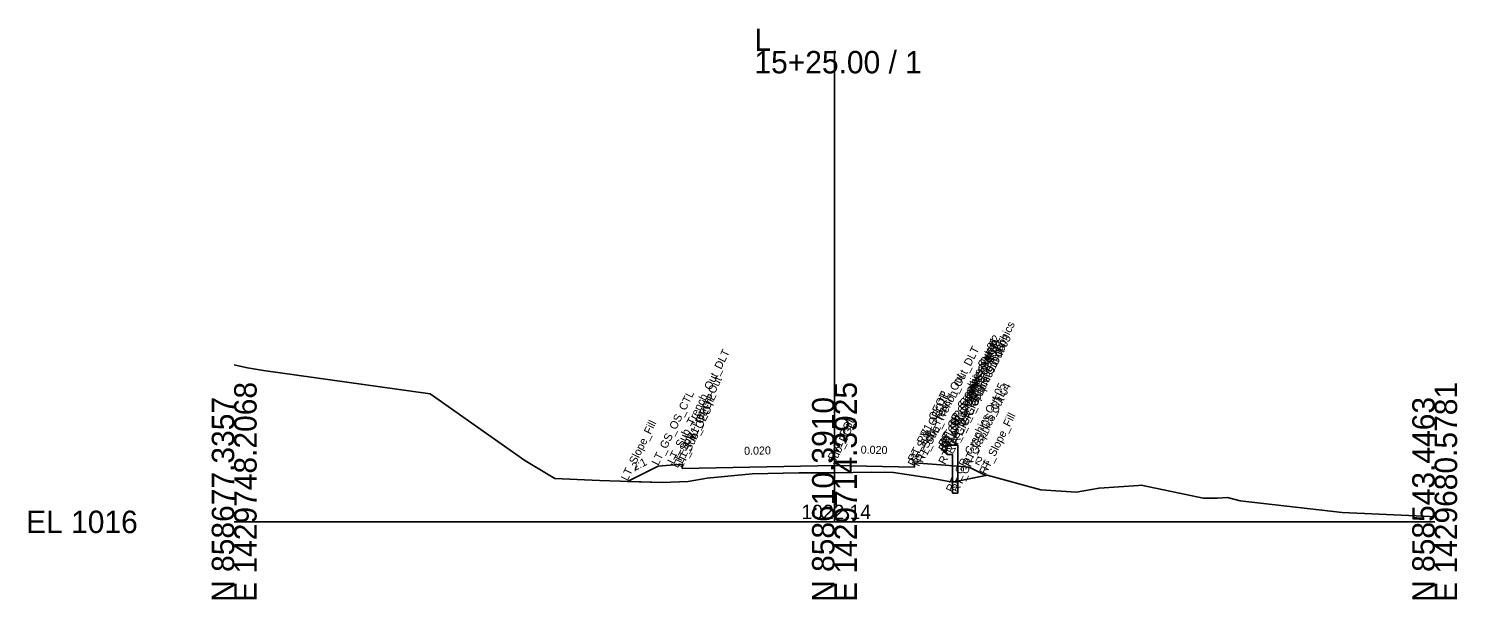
# Model space of a CAD drawing. Extents: x -26 to 176, y -10 to 13058.
# Drawn here: x -25.7 to 152.8, y 7490.3 to 7561.6 of the extents above; entities that cross this region are included whole.
import ezdxf

# ---------------------------------------------------------------- set-up
doc = ezdxf.new("R2010")
doc.units = 0
for name, color, linetype in [('Default', 7, 'Continuous'), ('Exist Cross Section Cell', 7, 'Continuous'), ('Exist XS Center Line Elevation Label', 7, 'Continuous'), ('Exist XS Ground Line', 7, 'Continuous'), ('Old_Level_50', 7, 'Continuous'), ('Prop CMT Guardrail Graphics', 7, 'Continuous'), ('Prop CMT Pvmt Course 1', 7, 'Continuous'), ('Prop CMT Pvmt Surface Shoulder', 7, 'Continuous'), ('Prop CMT Shld Paved Course 1', 7, 'Continuous'), ('Prop CMT Slope Grass', 7, 'Continuous'), ('Prop CMT Subgrade Earthwork', 7, 'Continuous'), ('Prop XS Dump Level', 7, 'Continuous'), ('Prop XS SE Text', 7, 'Continuous'), ('Prop XS Side Slope Text', 7, 'Continuous')]:
    doc.layers.add(name, color=color, linetype=linetype)

msp = doc.modelspace()

# ---------------------------------------------------------------- linework, layer by layer
at = {"layer": 'Exist Cross Section Cell'}
for p, q in [((75, 7500), (75, 7558.84)), ((0, 7500), (75, 7500)), ((75, 7500), (150, 7500))]:
    msp.add_line(p, q, dxfattribs=at)
at = {"layer": 'Exist XS Ground Line'}
msp.add_lwpolyline([(0, 7519.61), (0.71, 7519.47), (1.67, 7519.25), (3.65, 7518.93), (24.5, 7515.98), (36.31, 7507.68), (40.06, 7505.43), (45.63, 7505.15), (53.46, 7504.93), (56.72, 7505.03), (59.11, 7505.44), (64.72, 7506.01), (70.54, 7506.11), (73.64, 7506.13), (75, 7506.14), (79.63, 7506.19), (82.39, 7506.18), (87.07, 7505.47), (89.77, 7504.96), (94.08, 7505.83), (100.77, 7504.01), (105.19, 7503.69), (108.07, 7504.22), (113.01, 7504.56), (113.32, 7504.57), (119.69, 7503.26), (121.09, 7502.96), (122.86, 7502.97), (124.11, 7503.04), (125.68, 7502.64), (138.45, 7501.15), (148.62, 7500.7), (150, 7500.61)], dxfattribs=at)
at = {"layer": 'Old_Level_50'}
for points in [[(70.54, 7506.11), (73.64, 7506.13), (75, 7506.14), (79.63, 7506.19), (82.39, 7506.18), (87.07, 7505.47), (89.77, 7504.96), (93.93, 7505.79), (91.82, 7506.85), (88.82, 7507.09), (85, 7507.39), (85, 7506.85), (75, 7507.05), (55.98, 7506.67), (55.98, 7507.21), (52.98, 7506.97), (49.14, 7505.05), (53.46, 7504.93), (56.72, 7505.03), (59.11, 7505.44), (64.72, 7506.01)], [(91.82, 7506.85), (93.93, 7505.79), (89.77, 7504.96), (87.07, 7505.47), (82.39, 7506.18), (79.63, 7506.19), (75, 7506.14), (73.64, 7506.13), (70.54, 7506.11), (64.72, 7506.01), (59.11, 7505.44), (56.72, 7505.03), (53.46, 7504.93), (49.14, 7505.05), (52.98, 7506.97), (55.98, 7507.21), (55.98, 7506.67), (75, 7507.05), (85, 7506.85), (85, 7507.39), (88.82, 7507.09)]]:
    msp.add_lwpolyline(points, close=True, dxfattribs=at)
at = {"layer": 'Prop CMT Guardrail Graphics'}
for points in [[(90.42, 7509.59), (89.09, 7509.59), (88.82, 7509.3)], [(88.82, 7509.3), (89.09, 7509)], [(90.42, 7503.59), (90.42, 7509.59)], [(89.09, 7509), (88.82, 7508.71)], [(88.82, 7508.71), (89.09, 7508.42), (89.76, 7508.42)], [(89.76, 7508.42), (89.76, 7503.59)], [(89.76, 7503.59), (90.42, 7503.59)]]:
    msp.add_lwpolyline(points, dxfattribs=at)
at = {"layer": 'Prop CMT Pvmt Course 1'}
for points in [[(85, 7507.39), (85, 7506.85)], [(55.98, 7507.21), (55.98, 7506.67)], [(55.98, 7506.67), (75, 7507.05)], [(85, 7506.85), (75, 7507.05)]]:
    msp.add_lwpolyline(points, dxfattribs=at)
at = {"layer": 'Prop CMT Pvmt Surface Shoulder'}
for points in [[(85, 7507.39), (85, 7507.39)], [(55.98, 7507.21), (55.98, 7507.21)]]:
    msp.add_lwpolyline(points, dxfattribs=at)
at = {"layer": 'Prop CMT Shld Paved Course 1'}
for points in [[(85, 7507.39), (85, 7507.39)], [(85, 7506.85), (85, 7507.39)], [(55.98, 7507.21), (55.98, 7507.21)], [(55.98, 7506.67), (55.98, 7507.21)]]:
    msp.add_lwpolyline(points, dxfattribs=at)
at = {"layer": 'Prop CMT Slope Grass'}
for points in [[(85, 7507.39), (88.82, 7507.09)], [(55.98, 7507.21), (52.98, 7506.97), (49.14, 7505.05)], [(52.98, 7506.97), (49.14, 7505.05)], [(88.82, 7507.09), (91.82, 7506.85)], [(91.82, 7506.85), (93.93, 7505.79)]]:
    msp.add_lwpolyline(points, dxfattribs=at)
at = {"layer": 'Prop CMT Subgrade Earthwork'}
for points in [[(75, 7507.05), (55.98, 7506.67)], [(75, 7507.05), (85, 7506.85)]]:
    msp.add_lwpolyline(points, dxfattribs=at)

# ---------------------------------------------------------------- texts
at = {"layer": 'Default'}
msp.add_text('-', height=0.0001, dxfattribs=at).set_placement((0, 7500))
at = {"layer": 'Exist Cross Section Cell'}
for s, p in [('L', (65, 7558.84)), ('15+25.00 / 1', (65, 7556.04)), ('EL 1016', (-26, 7498.6))]:
    msp.add_text(s, height=2.8, dxfattribs=at).set_placement(p)
for s, p in [('E 1429748.2068', (2.8, 7490)), ('E 1429714.3925', (77.8, 7490)), ('E 1429680.5781', (152.8, 7490)), ('N 858677.3357', (0, 7490)), ('N 858610.3910', (75, 7490)), ('N 858543.4463', (150, 7490))]:
    msp.add_text(s, height=2.8, rotation=90, dxfattribs=at).set_placement(p)
at = {"layer": 'Exist XS Center Line Elevation Label'}
msp.add_text('1022.14', height=1.8, dxfattribs=at).set_placement((70.87, 7500.34))
msp.add_text('1022.14', height=1.8, dxfattribs=at).set_placement((70.87, 7500.34))
msp.add_text('1022.14', height=1.8, dxfattribs=at).set_placement((70.87, 7500.34))
at = {"layer": 'Prop XS Dump Level'}
for s, p in [('RT_GS_OS_GR_Face_Graphics', (88.82, 7507.09)), ('LT_Sub_Trench_Out_DLT', (54.95, 7507.13)), ('RT_Sub_Trench_Out_DLT', (86.02, 7507.31)), ('RT_GR_Graphics Out 01', (88.82, 7509.3)), ('RT_GR_Graphics Out 08', (88.82, 7508.71)), ('RT_GR_Graphics Out 02', (89.09, 7509.59)), ('RT_GR_Graphics Out 09', (89.09, 7509)), ('RT_GR_Graphics Out 07', (89.09, 7508.42)), ('RT_GR_Graphics Out 06', (89.76, 7508.42)), ('RT_GR_Graphics Out 03', (90.42, 7509.59)), ('LT_Sub_Trench_Out', (55.42, 7506.66)), ('RT_Sub_Trench_Out', (85.55, 7506.84)), ('RT_PV1_OEOT', (85, 7507.39)), ('RT_PS1_OEOP', (85, 7507.39)), ('RT_GR_Graphics Out 05', (89.76, 7503.59)), ('RT_GR_Graphics Out 04', (90.42, 7503.59)), ('LT_GS_OS_CTL', (52.98, 7506.97)), ('LT_PV1_OEOT', (55.98, 7507.21)), ('LT_PS1_OEOP', (55.98, 7507.21)), ('LT_Sub_OEOT', (55.98, 7506.67)), ('RT_Sub_OEOT', (85, 7506.85)), ('RT_GS_OS_CTL', (91.82, 7506.85)), ('LT_Slope_Fill', (49.14, 7505.05)), ('PV1_PGL', (75, 7507.59)), ('RT_Slope_Fill', (93.92, 7505.8)), ('Sub_PGL', (75, 7507.05))]:
    msp.add_text(s, height=1, rotation=63.5833, dxfattribs=at).set_placement(p)
at = {"layer": 'Prop XS SE Text'}
for rotation, p in [(1.1458, (63.72, 7508.37)), (358.8542, (78.27, 7508.53))]:
    msp.add_text('0.020', height=1, rotation=rotation, dxfattribs=at).set_placement(p)
at = {"layer": 'Prop XS Side Slope Text'}
for rotation, p in [(26.565, (50.01, 7506.33)), (333.4349, (92.5, 7507.35))]:
    msp.add_text('2:1', height=1, rotation=rotation, dxfattribs=at).set_placement(p)

doc.saveas('drawing.dxf')
